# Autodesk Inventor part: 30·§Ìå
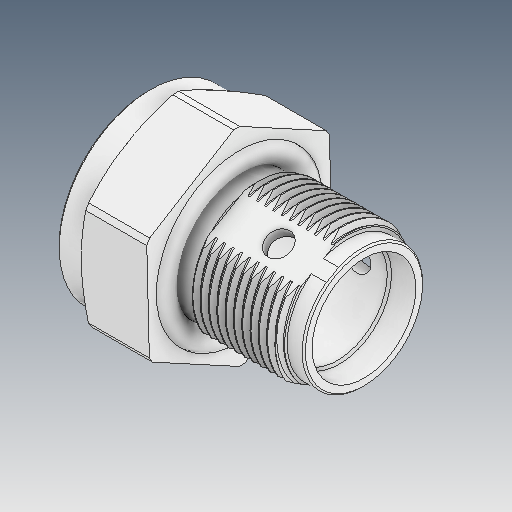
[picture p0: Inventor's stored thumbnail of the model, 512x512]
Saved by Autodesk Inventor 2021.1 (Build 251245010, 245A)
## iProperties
Created: 2021-05
Part Number: 30·§Ìå
Material: Ogólny
Document SubType Name: Modeling
Designer: user
Density: 1 g/cm^3
Appearance: Domyślna
Author: user
Revision Number: ÈÎºÎ
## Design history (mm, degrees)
feature "ÊäÈë1"
feature "ÊäÈë2"
node "Bryła1"
node "Bryła2"
